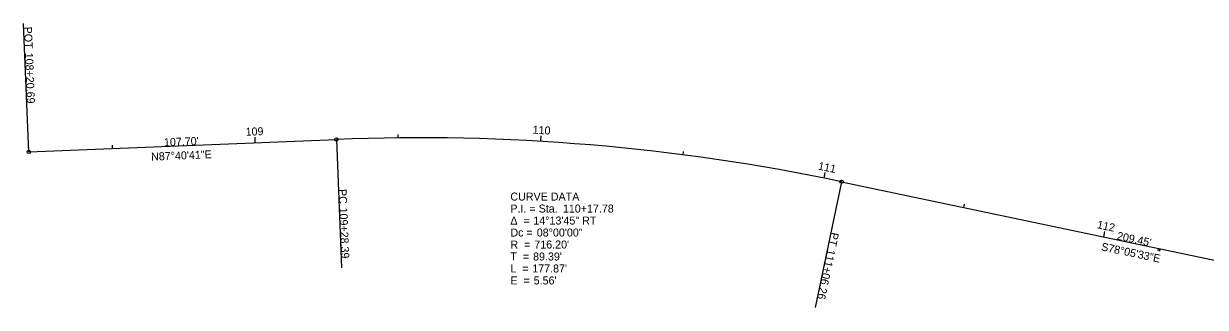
# Model space of a CAD drawing. Extents: x 2003596 to 2006888, y 572582 to 572983.
# Drawn here: x 2003595.8 to 2004009.3, y 572883.2 to 572982.7 of the extents above; entities that cross this region are included whole.
import ezdxf

# ---------------------------------------------------------------- set-up
doc = ezdxf.new("R2010")
doc.units = 0
for name, color, linetype in [('DR_X_Ditch', 7, 'Continuous'), ('DR_X_Erosion_Control', 7, 'Continuous'), ('DR_X_Headwall', 7, 'Continuous'), ('PM_X_CL_Double_Solid', 7, 'Continuous'), ('PM_X_Edge_Line', 7, 'Continuous'), ('PM_X_Surveyed_Line', 7, 'Continuous'), ('PV_X_COP', 7, 'Continuous'), ('PV_X_Driveway', 7, 'Continuous'), ('PV_X_EOP', 7, 'Continuous'), ('RD_X_Fence', 7, 'Continuous'), ('SV_X_Break_Lines', 7, 'Continuous'), ('SV_X_Top_of_Bank', 7, 'Continuous'), ('UT_X_Water', 7, 'Continuous'), ('UT_X_Water_Cells', 7, 'Continuous'), ('VG_X_Cells', 7, 'Continuous'), ('VG_X_Tree_Line_Lt', 7, 'Continuous'), ('XS_X_Ground_Line', 7, 'Continuous')]:
    doc.layers.add(name, color=color, linetype=linetype)

msp = doc.modelspace()

# ---------------------------------------------------------------- linework, layer by layer
at = {"layer": 'DR_X_Ditch'}
for p, q in [((2003676.85, 572940.94), (2003676.77, 572942.94)), ((2003726.82, 572942.64), (2003726.81, 572943.84)), ((2003776.8, 572941.42), (2003776.92, 572943.41)), ((2003626.89, 572938.92), (2003626.85, 572940.12)), ((2003826.56, 572936.71), (2003826.72, 572937.9)), ((2003875.88, 572928.54), (2003876.28, 572930.5)), ((2003924.81, 572918.25), (2003925.06, 572919.42)), ((2003973.74, 572907.93), (2003974.15, 572909.89))]:
    msp.add_line(p, q, dxfattribs=at)
at = {"layer": 'PM_X_Surveyed_Line'}
for p, q in [((2003597.61, 572937.73), (2003705.22, 572942.09)), ((2003882.01, 572927.27), (2004086.95, 572884.06))]:
    msp.add_line(p, q, dxfattribs=at)
msp.add_arc((2003734.24, 572226.48), 716.2, 78.09264, 92.32181, dxfattribs=at)
at = {"layer": 'PV_X_COP'}
for p, q in [((2003597.61, 572937.73), (2003595.79, 572982.69)), ((2003705.22, 572942.09), (2003707.04, 572897.13)), ((2003882.01, 572927.27), (2003872.72, 572883.24))]:
    msp.add_line(p, q, dxfattribs=at)
for centre in [(2003705.22, 572942.09), (2003597.61, 572937.73), (2003882.01, 572927.27)]:
    msp.add_circle(centre, 0.6, dxfattribs=at)
at = {"layer": 'RD_X_Fence'}
for p, q in [((2003676.85, 572940.94), (2003676.8, 572942.14)), ((2003776.8, 572941.42), (2003776.92, 572943.41)), ((2003875.88, 572928.54), (2003876.12, 572929.71)), ((2003973.74, 572907.93), (2003973.98, 572909.1))]:
    msp.add_line(p, q, dxfattribs=at)
at = {"layer": 'SV_X_Top_of_Bank'}
for p, q in [((2003597.61, 572937.73), (2003595.79, 572982.69)), ((2003705.22, 572942.09), (2003707.04, 572897.13)), ((2003882.01, 572927.27), (2003872.72, 572883.24))]:
    msp.add_line(p, q, dxfattribs=at)
for centre in [(2003705.22, 572942.09), (2003597.61, 572937.73), (2003882.01, 572927.27)]:
    msp.add_circle(centre, 0.6, dxfattribs=at)
at = {"layer": 'UT_X_Water_Cells'}
msp.add_line((2003776.8, 572941.42), (2003776.92, 572943.41), dxfattribs=at)
at = {"layer": 'VG_X_Cells'}
for p, q in [((2003992.57, 572903.41), (2003993.57, 572903.41)), ((2003993.07, 572903.91), (2003993.07, 572902.91)), ((2003993.07, 572903.41), (2003993.07, 572903.41))]:
    msp.add_line(p, q, dxfattribs=at)
at = {"layer": 'VG_X_Tree_Line_Lt'}
for p, q in [((2003597.61, 572937.73), (2003595.79, 572982.69)), ((2003705.22, 572942.09), (2003707.04, 572897.13)), ((2003882.01, 572927.27), (2003872.72, 572883.24))]:
    msp.add_line(p, q, dxfattribs=at)
for centre in [(2003705.22, 572942.09), (2003597.61, 572937.73), (2003882.01, 572927.27)]:
    msp.add_circle(centre, 0.6, dxfattribs=at)

# ---------------------------------------------------------------- texts
at = {"layer": 'DR_X_Ditch'}
for s, rotation, p in [('109', 2.3218, (2003673.5, 572943.36)), ('110', 356.593, (2003773.82, 572944.15)), ('111', 348.5931, (2003873.61, 572931.54)), ('112', 348.0925, (2003971.19, 572911.02))]:
    msp.add_text(s, height=2.8, rotation=rotation, dxfattribs=at).set_placement(p)
at = {"layer": 'DR_X_Erosion_Control'}
for s, p in [('CURVE DATA', (2003766.1, 572920.68)), ('P.I. = Sta. ', (2003766.1, 572916.48)), ('110+17.78', (2003784.47, 572916.48)), ('Δ  = ', (2003766.1, 572912.28)), ('14°13\'45" RT', (2003774.13, 572912.28)), ('Dc = ', (2003766.1, 572908.08)), ('08°00\'00"', (2003775.34, 572908.08)), ('R  = ', (2003766.1, 572903.88)), ("716.20'", (2003774.47, 572903.88)), ('T  = ', (2003766.1, 572899.68)), ("89.39'", (2003774.04, 572899.68)), ('L  = ', (2003766.1, 572895.48)), ("177.87'", (2003773.75, 572895.48)), ('E  = ', (2003766.1, 572891.28)), ("5.56'", (2003774.26, 572891.28))]:
    msp.add_text(s, height=2.8, dxfattribs=at).set_placement(p)
at = {"layer": 'DR_X_Headwall'}
for s, p in [('CURVE DATA', (2003766.1, 572920.68)), ('P.I. = Sta. ', (2003766.1, 572916.48)), ('110+17.78', (2003784.47, 572916.48)), ('Δ  = ', (2003766.1, 572912.28)), ('14°13\'45" RT', (2003774.13, 572912.28)), ('Dc = ', (2003766.1, 572908.08)), ('08°00\'00"', (2003775.34, 572908.08)), ('R  = ', (2003766.1, 572903.88)), ("716.20'", (2003774.47, 572903.88)), ('T  = ', (2003766.1, 572899.68)), ("89.39'", (2003774.04, 572899.68)), ('L  = ', (2003766.1, 572895.48)), ("177.87'", (2003773.75, 572895.48)), ('E  = ', (2003766.1, 572891.28)), ("5.56'", (2003774.26, 572891.28))]:
    msp.add_text(s, height=2.8, dxfattribs=at).set_placement(p)
at = {"layer": 'PM_X_CL_Double_Solid'}
for s, rotation, p in [("107.70'", 2.3218, (2003644.93, 572939.7)), ("209.45'", 348.0925, (2003978.14, 572907.05))]:
    msp.add_text(s, height=2.8, rotation=rotation, dxfattribs=at).set_placement(p)
at = {"layer": 'PM_X_Edge_Line'}
for s, rotation, p in [("107.70'", 2.3218, (2003644.93, 572939.7)), ("209.45'", 348.0925, (2003978.14, 572907.05))]:
    msp.add_text(s, height=2.8, rotation=rotation, dxfattribs=at).set_placement(p)
at = {"layer": 'PV_X_COP'}
for s, rotation, p in [('POT', 272.3218, (2003595.88, 572981.55)), ('108+20.69', 272.3218, (2003596.25, 572972.43)), ('PC', 272.3218, (2003705.97, 572924.66)), ('109+28.39', 272.3218, (2003706.24, 572918.14)), ('PT', 258.0925, (2003878.36, 572909.72)), ('111+06.26', 258.0925, (2003877.1, 572903.76))]:
    msp.add_text(s, height=2.8, rotation=rotation, dxfattribs=at).set_placement(p)
at = {"layer": 'PV_X_Driveway'}
for s, p in [('CURVE DATA', (2003766.1, 572920.68)), ('P.I. = Sta. ', (2003766.1, 572916.48)), ('110+17.78', (2003784.47, 572916.48)), ('Δ  = ', (2003766.1, 572912.28)), ('14°13\'45" RT', (2003774.13, 572912.28)), ('Dc = ', (2003766.1, 572908.08)), ('08°00\'00"', (2003775.34, 572908.08)), ('R  = ', (2003766.1, 572903.88)), ("716.20'", (2003774.47, 572903.88)), ('T  = ', (2003766.1, 572899.68)), ("89.39'", (2003774.04, 572899.68)), ('L  = ', (2003766.1, 572895.48)), ("177.87'", (2003773.75, 572895.48)), ('E  = ', (2003766.1, 572891.28)), ("5.56'", (2003774.26, 572891.28))]:
    msp.add_text(s, height=2.8, dxfattribs=at).set_placement(p)
at = {"layer": 'PV_X_EOP'}
for s, rotation, p in [('N87°40\'41"E', 2.3218, (2003640.44, 572934.66)), ('S78°05\'33"E', 348.0925, (2003972.65, 572903.25))]:
    msp.add_text(s, height=2.8, rotation=rotation, dxfattribs=at).set_placement(p)
at = {"layer": 'RD_X_Fence'}
msp.add_text('110', height=2.8, rotation=356.593, dxfattribs=at).set_placement((2003773.82, 572944.15))
at = {"layer": 'SV_X_Break_Lines'}
for s, rotation, p in [('N87°40\'41"E', 2.3218, (2003640.44, 572934.66)), ('S78°05\'33"E', 348.0925, (2003972.65, 572903.25))]:
    msp.add_text(s, height=2.8, rotation=rotation, dxfattribs=at).set_placement(p)
at = {"layer": 'SV_X_Top_of_Bank'}
for s, rotation, p in [('POT', 272.3218, (2003595.88, 572981.55)), ('108+20.69', 272.3218, (2003596.25, 572972.43)), ('PC', 272.3218, (2003705.97, 572924.66)), ('109+28.39', 272.3218, (2003706.24, 572918.14)), ('PT', 258.0925, (2003878.36, 572909.72)), ('111+06.26', 258.0925, (2003877.1, 572903.76))]:
    msp.add_text(s, height=2.8, rotation=rotation, dxfattribs=at).set_placement(p)
at = {"layer": 'UT_X_Water'}
for s, rotation, p in [('N87°40\'41"E', 2.3218, (2003640.44, 572934.66)), ('S78°05\'33"E', 348.0925, (2003972.65, 572903.25))]:
    msp.add_text(s, height=2.8, rotation=rotation, dxfattribs=at).set_placement(p)
at = {"layer": 'UT_X_Water_Cells'}
msp.add_text('110', height=2.8, rotation=356.593, dxfattribs=at).set_placement((2003773.82, 572944.15))
at = {"layer": 'VG_X_Tree_Line_Lt'}
for s, rotation, p in [('POT', 272.3218, (2003595.88, 572981.55)), ('108+20.69', 272.3218, (2003596.25, 572972.43)), ('PC', 272.3218, (2003705.97, 572924.66)), ('109+28.39', 272.3218, (2003706.24, 572918.14)), ('PT', 258.0925, (2003878.36, 572909.72)), ('111+06.26', 258.0925, (2003877.1, 572903.76))]:
    msp.add_text(s, height=2.8, rotation=rotation, dxfattribs=at).set_placement(p)
at = {"layer": 'XS_X_Ground_Line'}
for s, rotation, p in [("107.70'", 2.3218, (2003644.93, 572939.7)), ("209.45'", 348.0925, (2003978.14, 572907.05))]:
    msp.add_text(s, height=2.8, rotation=rotation, dxfattribs=at).set_placement(p)

doc.saveas('drawing.dxf')
